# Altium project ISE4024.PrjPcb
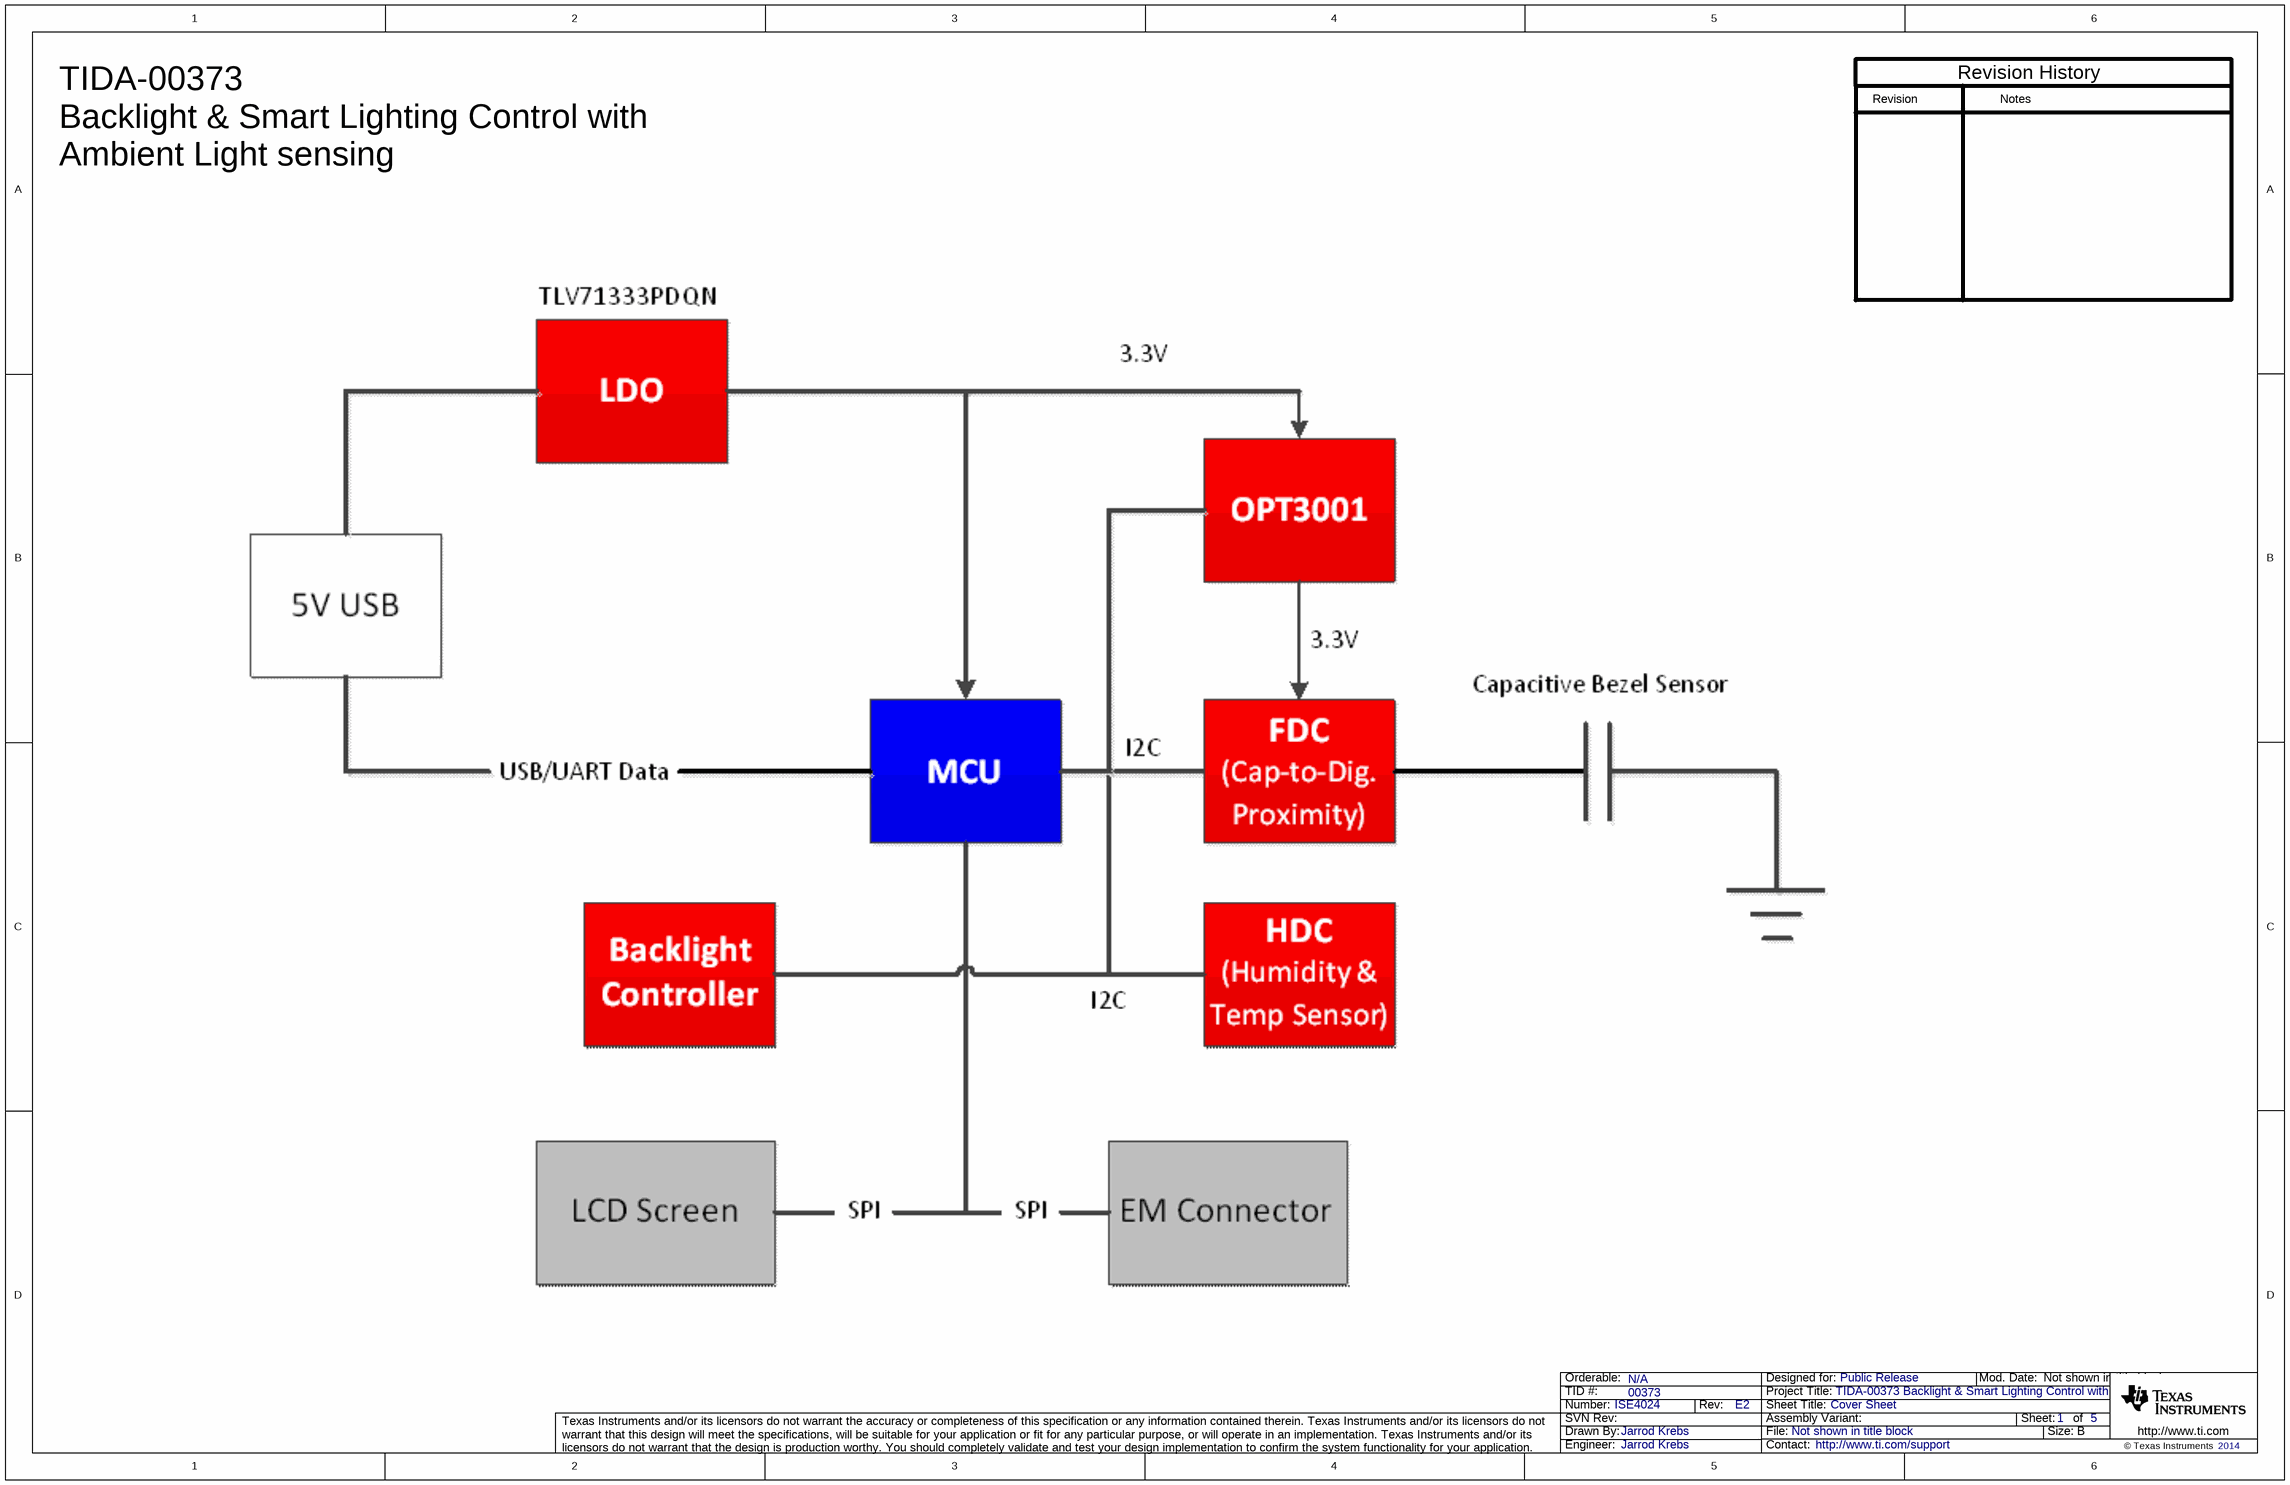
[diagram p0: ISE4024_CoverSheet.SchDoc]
CopyrightYear: 2014; EVM_Orderable: N/A; PCB_Rev: E2; PRJ_Customer: Public Release; PRJ_Engineer: Jarrod Krebs; PRJ_Number: ISE4024; PRJ_Title: TIDA-00373 Backlight & Smart Lighting Control with Ambient Light Sensing; SCH_Rev: E2; TechSupport: http://www.ti.com/support; TID: 00373
5 sheets, 138 parts. Net scope: global (net labels, ports and power ports of the same name join across sheets).
Board file: ISE4024_TID.PcbDoc
Sheets:
  ISE4024_CoverSheet.SchDoc
  ISE4024_TID_Hardware.SchDoc
  ISE4024_Sheet1.SchDoc
  ISE4024_Sheet2.SchDoc
  ISE4024_Sheet3.SchDoc

## Sheet ISE4024_CoverSheet.SchDoc: Cover Sheet
size 431 x 279 mm; Date: Not shown in title block; ApprovedBy: Not shown in title block; CheckedBy: Not shown in title block; Author: Not shown in title block; CompanyName: Not shown in title block; DrawnBy: Jarrod Krebs; Engineer: Not shown in title block; Organization: Not shown in title block; Address1: Not shown in title block; Address2: Not shown in title block; Address3: Not shown in title block; Address4: Not shown in title block; DocumentNumber: 1; Revision: Use project parameter SCH_Rev; SheetNumber: 1; SheetTotal: 5; PageSetup: Record=PageOptions¦CenterHorizontal=True¦CenterVertical=True¦PrintScale=1.00¦XCorrection=1.00¦YCorrection=1.00¦PrintKind=0¦BorderSize=5000000¦LeftOffset=0¦BottomOffset=0¦Orientation=2¦PaperLength=1000¦PaperWidth=1000¦Scale=100¦PaperSource=15¦PrintQuality=600¦MediaType=1¦DitherType=10¦PaperKind=Letter¦PrintScaleMode=1

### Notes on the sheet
- Revision
- Notes
- Revision History
- TIDA-00373
  Backlight & Smart Lighting Control with
  Ambient Light sensing

## Sheet ISE4024_TID_Hardware.SchDoc: Hardware
size 431 x 279 mm; Date: Not shown in title block; ApprovedBy: Not shown in title block; CheckedBy: Not shown in title block; Author: Not shown in title block; CompanyName: Not shown in title block; DrawnBy: Jarrod Krebs; Engineer: Not shown in title block; Organization: Not shown in title block; Address1: Not shown in title block; Address2: Not shown in title block; Address3: Not shown in title block; Address4: Not shown in title block; DocumentNumber: 2; Revision: Use project parameter SCH_Rev; SheetNumber: 2; SheetTotal: 5; PageSetup: Record=PageOptions¦CenterHorizontal=True¦CenterVertical=True¦PrintScale=1.00¦XCorrection=1.00¦YCorrection=1.00¦PrintKind=0¦BorderSize=5000000¦LeftOffset=0¦BottomOffset=0¦Orientation=2¦PaperLength=1000¦PaperWidth=1000¦Scale=100¦PaperSource=15¦PrintQuality=600¦MediaType=1¦DitherType=10¦PaperKind=Letter¦PrintScaleMode=1
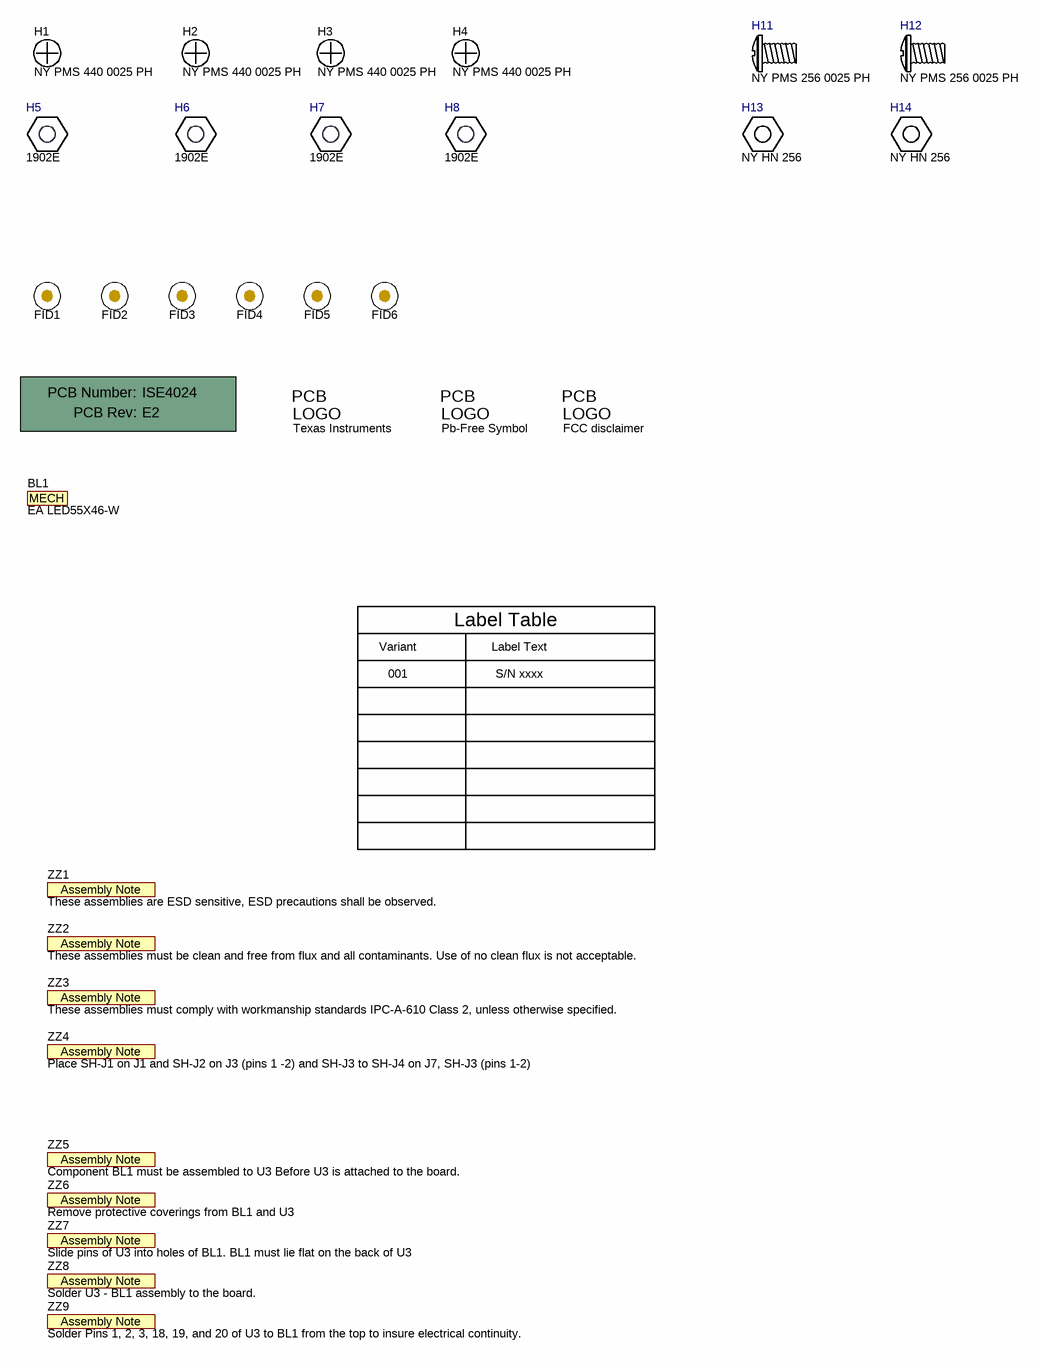
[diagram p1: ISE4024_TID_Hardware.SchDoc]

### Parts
!PCB  Printed Circuit Board  (value not drawn)  (mechanical)
BL1  EA LED55X46-W  (mechanical)
FID1  Fiducial  [Fiducial10-20]  (value not drawn)
FID2  Fiducial  [Fiducial10-20]  (value not drawn)
FID3  Fiducial  [Fiducial10-20]  (value not drawn)
FID4  Fiducial  [Fiducial10-20]  (value not drawn)
FID5  Fiducial  [Fiducial10-20]  (value not drawn)
FID6  Fiducial  [Fiducial10-20]  (value not drawn)
H1  NY PMS 440 0025 PH  [NY PMS 440 0025 PH]
H2  NY PMS 440 0025 PH  [NY PMS 440 0025 PH]
H3  NY PMS 440 0025 PH  [NY PMS 440 0025 PH]
H4  NY PMS 440 0025 PH  [NY PMS 440 0025 PH]
H5  1902E  [Keystone_1902E]
H6  1902E  [Keystone_1902E]
H7  1902E  [Keystone_1902E]
H8  1902E  [Keystone_1902E]
H11  NY PMS 256 0025 PH  (mechanical)
H12  NY PMS 256 0025 PH  (mechanical)
H13  NY HN 256  (mechanical)
H14  NY HN 256  (mechanical)
Logo1  Texas Instruments  [TI_Stacked_Overlay_Medium]  (no BOM)
Logo2  Pb-Free Symbol  [Pb-Free_Overlay_Small]  (no BOM)
Logo3  FCC disclaimer  [FCC_disclaimer]  (no BOM)
ZZ1  These assemblies are ESD sensitive, ESD precautions shall be observed.  [AssemblyNote]  (no BOM)
ZZ2  These assemblies must be clean and free from flux and all contaminants. Use of no clean flux is not acceptable.  [AssemblyNote]  (no BOM)
ZZ3  These assemblies must comply with workmanship standards IPC-A-610 Class 2, unless otherwise specified.  [AssemblyNote]  (no BOM)
ZZ4  Place SH-J1 on J1 and SH-J2 on J3 (pins 1 -2) and SH-J3 to SH-J4 on J7, SH-J3 (pins 1-2)  [AssemblyNote]  (no BOM)
ZZ5  Component BL1 must be assembled to U3 Before U3 is attached to the board.  [AssemblyNote]  (no BOM)
ZZ6  Remove protective coverings from BL1 and U3  [AssemblyNote]  (no BOM)
ZZ7  Slide pins of U3 into holes of BL1. BL1 must lie flat on the back of U3  [AssemblyNote]  (no BOM)
ZZ8  Solder U3 - BL1 assembly to the board.  [AssemblyNote]  (no BOM)
ZZ9  Solder Pins 1, 2, 3, 18, 19, and 20 of U3 to BL1 from the top to insure electrical continuity.  [AssemblyNote]  (no BOM)

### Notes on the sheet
- Variant
- Label Table
- Label Text
- 001
- S/N xxxx

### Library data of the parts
!PCB = PCB: Manufacturer: Any; PartNumber: ISE4024; SymbolCreator: a0412235
BL1 = EA LED55X46-W: LED Backlight, White; Manufacturer: Electronic Assembly; SymbolCreator: codlsc
FID1-FID6 = Fiducial: Fiducial mark.  There is nothing to buy or mount.; SymbolCreator: codlsc
H1-H4 = NY PMS 440 0025 PH: Machine Screw, Round, #4-40 x 1/4, Nylon, Philips panhead; Manufacturer: B&F Fastener Supply; CompType: Hardware; SymbolCreator: codlsc; U/M: EA
H5-H8 = 1902E: Standoff, Hex, 1"L #4-40 Nylon; Manufacturer: Keystone; CompType: Hardware; SymbolCreator: a0412235
H11 H12 = NY PMS 256 0025 PH: Nylon Screw, Panhead, Phillips, 2-56; Manufacturer: B&F Fastener Supply; SymbolCreator: a0412235
H13 H14 = NY HN 256: Nylon Nut, 2-56, 3/16"; Manufacturer: B&F Fastener Supply; SymbolCreator: a0412235
Logo1 = TI_Logo: Texas Instrument Corporate Signature; SymbolCreator: codlsc
Logo2 = Pb-Free: SymbolCreator: a0412235
Logo3 = FCC_disclaimer: SymbolCreator: codlsc
ZZ1-ZZ3 = AssemblyNote: SymbolCreator: codlsc
ZZ4 = Assembly Note: This Assembly Note will show in the PcbDoc and associated outputs; SymbolCreator: codlsc
ZZ5 = AssemblyNote: Component BL1 must be assembled to U5 Before U5 is attached to the board.; SymbolCreator: codlsc
ZZ6 = AssemblyNote: Remove protective coverings from BL1 and U5; SymbolCreator: codlsc
ZZ7 = AssemblyNote: Slide pins of U5 into holes of BL1. BL1 must lie flat on the back of U5.; SymbolCreator: codlsc
ZZ8 = AssemblyNote: Solder U5 - BL1 assembly to the board.; SymbolCreator: codlsc
ZZ9 = AssemblyNote: Solder Pins 1, 2, 3, 18, 19, and 20 of U5 to BL1 from the top to insure electrical continuity.; SymbolCreator: codlsc

## Sheet ISE4024_Sheet1.SchDoc: Power and Display
size 431 x 279 mm; Date: Not shown in title block; ApprovedBy: Not shown in title block; CheckedBy: Not shown in title block; Author: Not shown in title block; CompanyName: Not shown in title block; DrawnBy: Jarrod Krebs; Engineer: Not shown in title block; Organization: Not shown in title block; Address1: Not shown in title block; Address2: Not shown in title block; Address3: Not shown in title block; Address4: Not shown in title block; DocumentNumber: 3; Revision: Use project parameter SCH_Rev; SheetNumber: 3; SheetTotal: 5; PageSetup: Record=PageOptions¦CenterHorizontal=True¦CenterVertical=True¦PrintScale=1.00¦XCorrection=1.00¦YCorrection=1.00¦PrintKind=0¦BorderSize=5000000¦LeftOffset=0¦BottomOffset=0¦Orientation=2¦PaperLength=1000¦PaperWidth=1000¦Scale=100¦PaperSource=15¦PrintQuality=600¦MediaType=1¦DitherType=10¦PaperKind=Letter¦PrintScaleMode=1
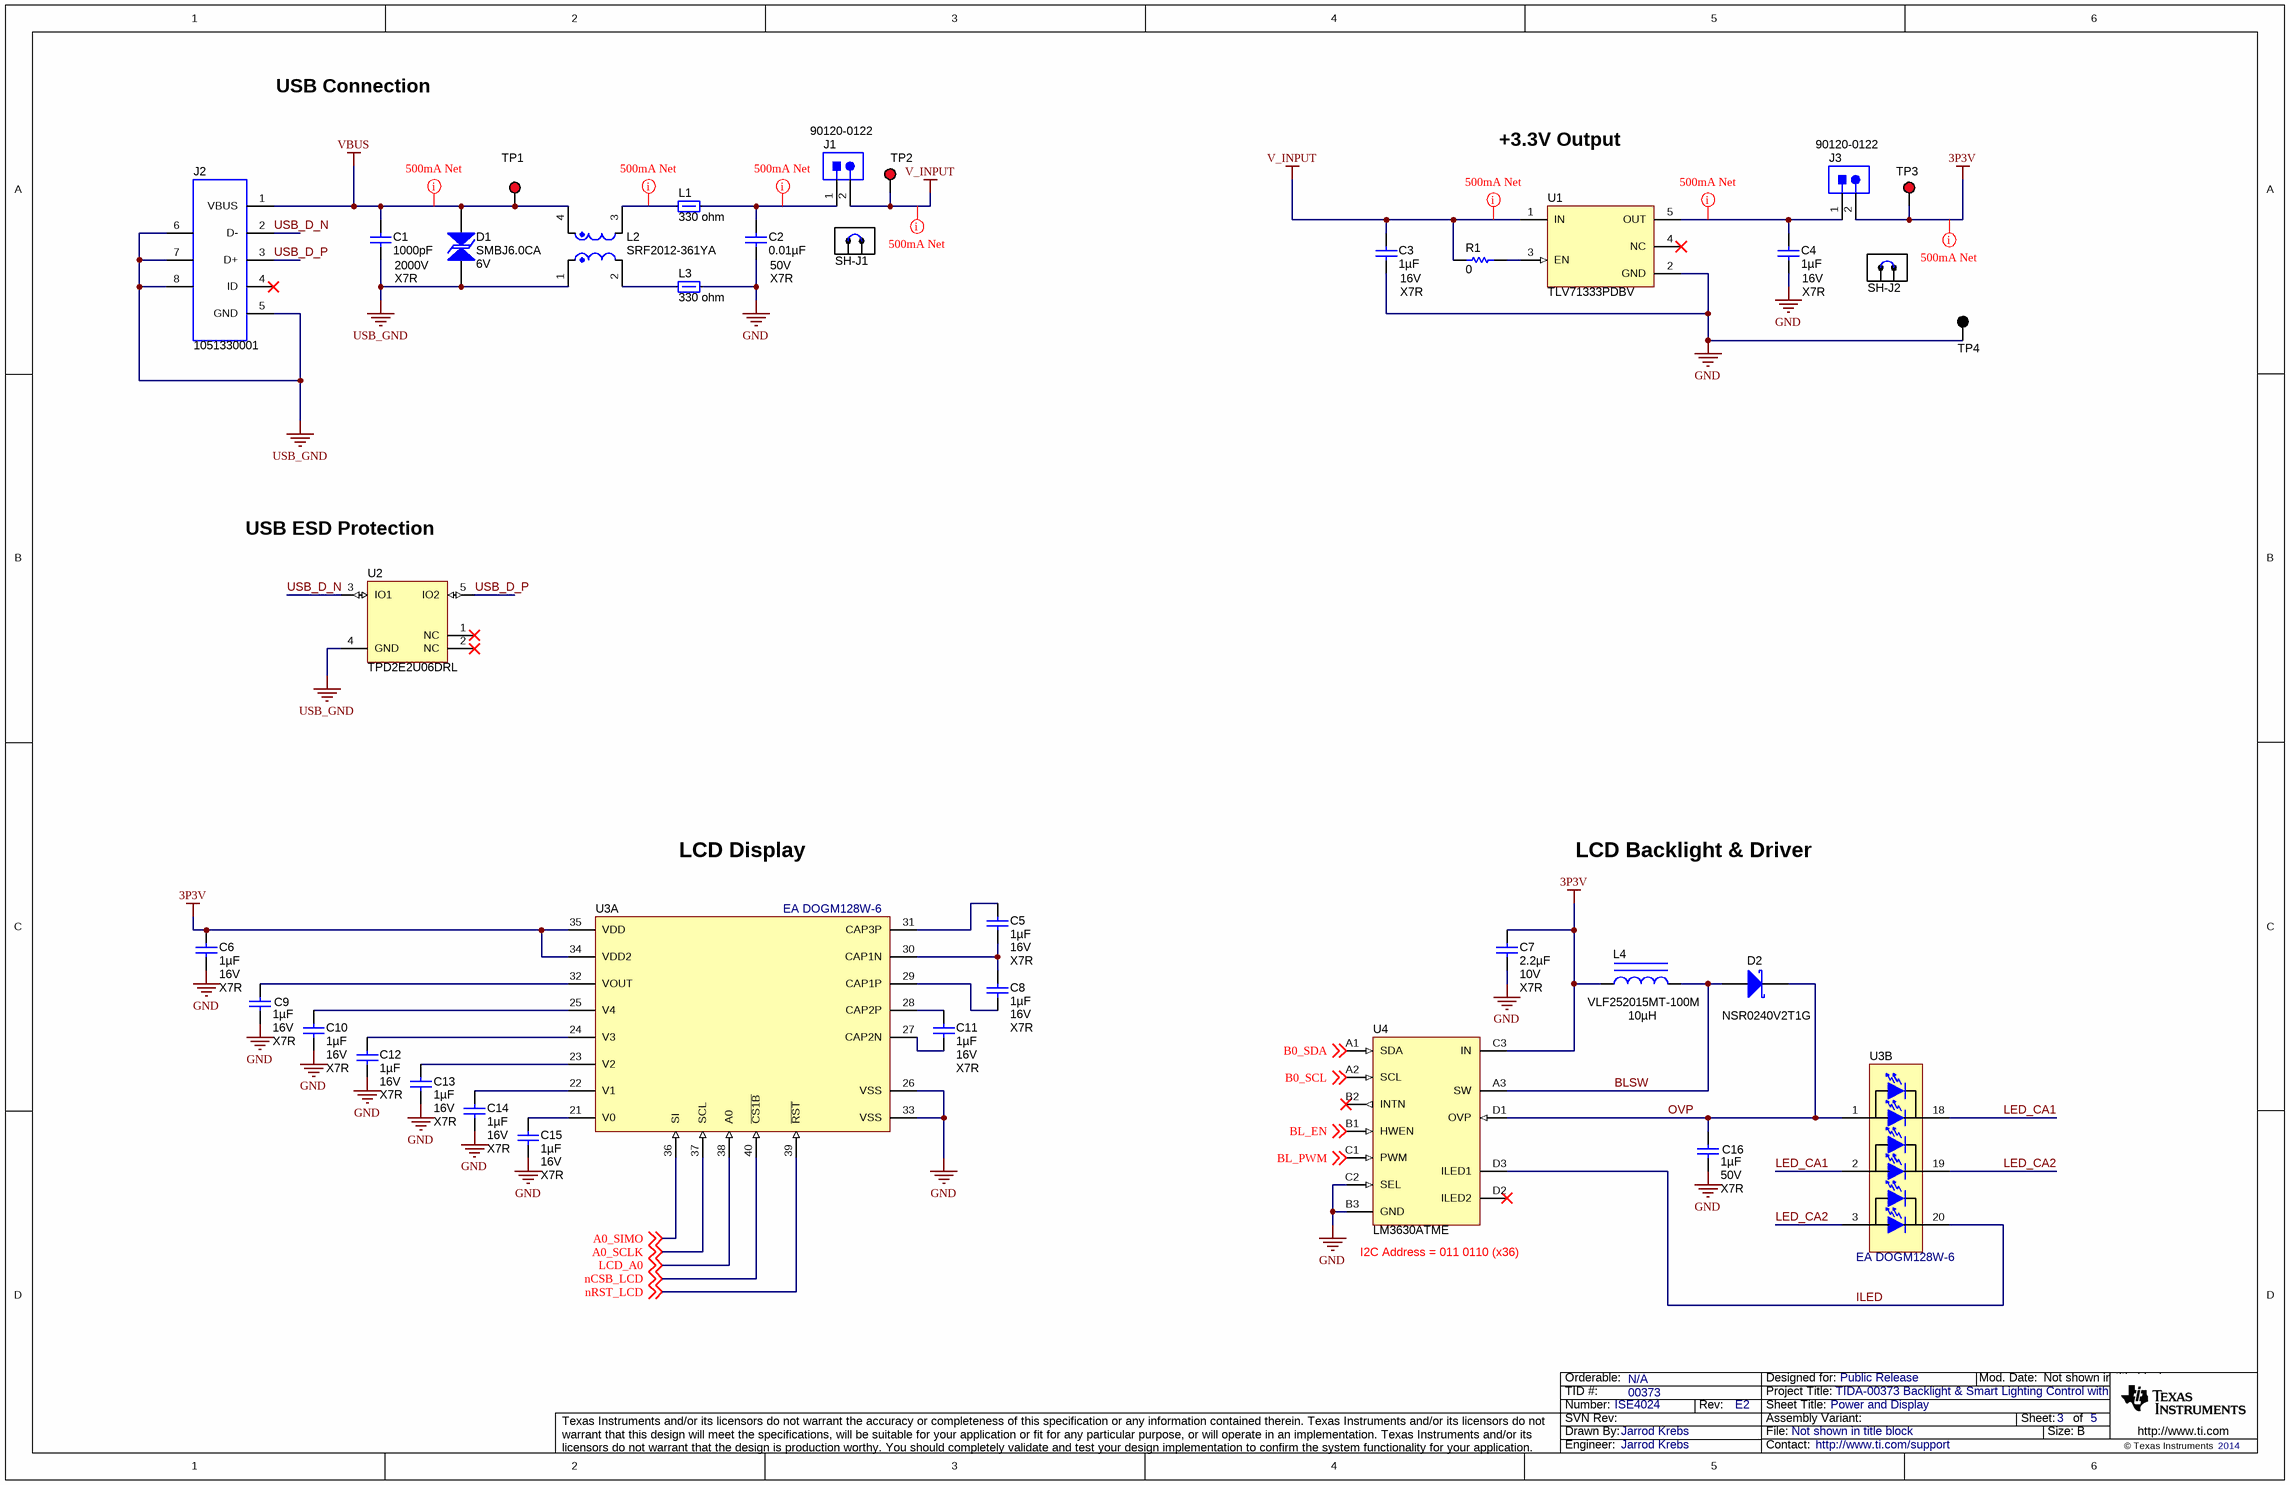
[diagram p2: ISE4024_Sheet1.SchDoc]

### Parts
C1  VDC_V: 2000V  TempCo: X7R  ValueDisplayed: 1000pF  [1206_190]  (hidden comment: 202R18W102KV4E)
C2  ValueDisplayed: 0.01µF  Value2: 50V  TempCo: X7R  [0805_HV]  (hidden comment: 08055C103JAT2A)
C3  ValueDisplayed: 1µF  Value2: 16V  TempCo: X7R  [0603]  (hidden comment: C1608X7R1C105K)
C4  ValueDisplayed: 1µF  Value2: 16V  TempCo: X7R  [0603]  (hidden comment: C1608X7R1C105K)
C5  ValueDisplayed: 1µF  Value2: 16V  TempCo: X7R  [0603]  (hidden comment: C1608X7R1C105K)
C6  ValueDisplayed: 1µF  Value2: 16V  TempCo: X7R  [0603]  (hidden comment: C1608X7R1C105K)
C7  ValueDisplayed: 2.2µF  Value2: 10V  TempCo: X7R  [0603]  (hidden comment: GRM188R71A225KE15D)
C8  ValueDisplayed: 1µF  Value2: 16V  TempCo: X7R  [0603]  (hidden comment: C1608X7R1C105K)
C9  ValueDisplayed: 1µF  Value2: 16V  TempCo: X7R  [0603]  (hidden comment: C1608X7R1C105K)
C10  ValueDisplayed: 1µF  Value2: 16V  TempCo: X7R  [0603]  (hidden comment: C1608X7R1C105K)
C11  ValueDisplayed: 1µF  Value2: 16V  TempCo: X7R  [0603]  (hidden comment: C1608X7R1C105K)
C12  ValueDisplayed: 1µF  Value2: 16V  TempCo: X7R  [0603]  (hidden comment: C1608X7R1C105K)
C13  ValueDisplayed: 1µF  Value2: 16V  TempCo: X7R  [0603]  (hidden comment: C1608X7R1C105K)
C14  ValueDisplayed: 1µF  Value2: 16V  TempCo: X7R  [0603]  (hidden comment: C1608X7R1C105K)
C15  ValueDisplayed: 1µF  Value2: 16V  TempCo: X7R  [0603]  (hidden comment: C1608X7R1C105K)
C16  ValueDisplayed: 1µF  Value2: 50V  TempCo: X7R  [0603]  (hidden comment: UMK107AB7105KA-T)
D1  SMBJ6.0CA  value 6V  [SMB]
D2  NSR0240V2T1G  [SOD-523]
J1  90120-0122  [CONN_90120-0122]
J2  1051330001  [Molex_1051330001]
J3  90120-0122  [CONN_90120-0122]
L1  value 330 ohm  [0603]  (hidden comment: BLM18SG331TN1D)
L2  SRF2012-361YA  [SRF2012A]
L3  value 330 ohm  [0603]  (hidden comment: BLM18SG331TN1D)
L4  VLF252015MT-100M  ValueDisplayed: 10µH  [IND_VLF252015]
R1  ValueDisplayed: 0  [0603]  (hidden comment: CRCW06030000Z0EA)
SH-J1  2SN-BK-G  [2SN-BK-G]  (value not drawn)
SH-J2  2SN-BK-G  [2SN-BK-G]  (value not drawn)
TP1  5000  [Keystone5000]  (value not drawn)
TP2  5000  [Keystone5000]  (value not drawn)
TP3  5000  [Keystone5000]  (value not drawn)
TP4  5001  [Keystone5001]  (value not drawn)
U1  TLV71333PDBV  [DBV0005A_N]
U2  TPD2E2U06DRL  [DRL0005A]
U3  EA DOGM128W-6  [LCD-MODULE_EA DOGM128W-6]  (parts A,B of 2)
U4  LM3630ATME  [YFQ0012AKAR]

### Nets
3P3V: C6.1 C7.1 J3.2 L4.1 TP3.1 U3.34(VDD2) U3.35(VDD) U4.C3(IN)
GND: C2.2 C3.2 C4.2 C6.2 C7.2 C9.2 C10.2 C12.2 C13.2 C14.2 C15.2 C16.2 L3.2 TP4.1 U1.2(GND) U3.26(VSS) U3.33(VSS) U4.B3(GND) U4.C2(SEL)
USB_GND: C1.2 D1.1 J2.5(GND) J2.6(Shield) J2.7(Shield) J2.8(Shield) L2.1 U2.4(GND)
V_INPUT: C3.1 J1.2 R1.1 TP2.1 U1.1(IN)
VBUS: C1.1 D1.2 J2.1(VBUS) L2.4 TP1.1
A0_SCLK: U3.37(SCL) ; off-sheet A0_SCLK
A0_SIMO: U3.36(SI) ; off-sheet A0_SIMO
B0_SCL: U4.A2(SCL) ; off-sheet B0_SCL
B0_SDA: U4.A1(SDA) ; off-sheet B0_SDA
BL_EN: U4.B1(HWEN) ; off-sheet BL_EN
BL_PWM: U4.C1(PWM) ; off-sheet BL_PWM
BLSW: D2.2(A) L4.2 U4.A3(SW)
ILED: U3.20(K) U4.D3(ILED1)
LCD_A0: U3.38(A0) ; off-sheet LCD_A0
LED_CA1: U3.2(A) U3.18(K)
LED_CA2: U3.3(A) U3.19(K)
nCSB_LCD: U3.40(~{CS1B}) ; off-sheet nCSB_LCD
nRST_LCD: U3.39(~{RST}) ; off-sheet nRST_LCD
OVP: C16.1 D2.1(K) U3.1(A) U4.D1(OVP)
USB_D_N: J2.2(D-) U2.3(IO1)
USB_D_P: J2.3(D+) U2.5(IO2)
NetC2_1: C2.1 J1.1 L1.2
NetC4_1: C4.1 J3.1 U1.5(OUT)
NetC5_1: C5.1 U3.31(CAP3P)
NetC5_2: C5.2 C8.1 U3.30(CAP1N)
NetC8_2: C8.2 U3.29(CAP1P)
NetC9_1: C9.1 U3.32(VOUT)
NetC10_1: C10.1 U3.25(V4)
NetC11_1: C11.1 U3.28(CAP2P)
NetC11_2: C11.2 U3.27(CAP2N)
NetC12_1: C12.1 U3.24(V3)
NetC13_1: C13.1 U3.23(V2)
NetC14_1: C14.1 U3.22(V1)
NetC15_1: C15.1 U3.21(V0)
NetL1_1: L1.1 L2.3
NetL2_2: L2.2 L3.1
NetR1_2: R1.2 U1.3(EN)

Not connected (* = marked no-connect by the designer): J2 4(ID)*; U1 4(NC)*; U2 1(NC)* 2(NC)*; U4 B2(INTN)* D2(ILED2)*

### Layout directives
rule Width Constraint [Pref Width = 25mil    Min Width = 5mil    Max Width = 100mil]: 3P3V, NetC2_1, NetC4_1, NetL1_1, V_INPUT, VBUS

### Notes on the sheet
- USB Connection
- +3.3V Output
- USB ESD Protection
- LCD Display
- LCD Backlight & Driver
- (near U4) I2C Address = 011 0110 (x36)

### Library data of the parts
C1 = 202R18W102KV4E: CAP, CERM, 1000 pF, 2000 V, +/- 10%, X7R, 1206_190; Manufacturer: Johanson Technology; Polarized: N; CompType: Capacitor; Value: 1000pF; U/M: EA; Cap_F: 0.000000001; Tolerance_%: 10; Value1: Unknown; TaMin_C: -55; TaMax_C: 125
C2 = 08055C103JAT2A: CAP, CERM, 0.01 µF, 50 V, +/- 5%, X7R, 0805; Manufacturer: AVX; Polarized: N; CompType: Capacitor; Value: 0.01uF; U/M: EA; Cap_F: 0.00000001; Tolerance_%: 5; ESR_ohm: 0.078; Value1: 0.078 ohm; VDC_V: 50; TaMin_C: -55; TaMax_C: 125; Cap_Case: 0805
C3 C4 = C1608X7R1C105K: CAP, CERM, 1 µF, 16 V, +/- 10%, X7R, 0603; Manufacturer: TDK; Polarized: N; CompType: Capacitor; Value: 1uF; U/M: EA; Cap_F: 0.000001; Tolerance_%: 10; ESR_ohm: 0.0057; Value1: 0.0057 ohm; VDC_V: 16; TaMin_C: -55; TaMax_C: 125
C5 C6 C8-C15 = C1608X7R1C105K: CAP, CERM, 1uF, 16V, +/-10%, X7R, 0603; Manufacturer: TDK; Polarized: N; CompType: Capacitor; U/M: EA; Cap_F: 0.000001; Tolerance_%: 10; ESR_Ohm: 0.0057; Value1: 0.0057 ohm; VDC_V: 16; TaMin_C: -55; TaMax_C: 125
C7 = GRM188R71A225KE15D: CAP, CERM, 2.2uF, 10V, +/-10%, X7R, 0603; Manufacturer: MuRata; Polarized: N; CompType: Capacitor; U/M: EA; Cap_F: 0.0000022; Tolerance_%: 10; ESR_Ohm: 0.009; Value1: 0.009 ohm; TaMin_C: -55; TaMax_C: 125
C16 = UMK107AB7105KA-T: CAP, CERM, 1uF, 50V, +/-10%, X7R, 0603; Manufacturer: Taiyo Yuden; Polarized: N; CompType: Capacitor; U/M: EA; Cap_F: 0.000001; Tolerance_%: 10; Value1: Unknown; VDC_V: 50; TaMin_C: -55; TaMax_C: 125
D1 = SMBJ6.0CA: Diode, TVS, Bi, 6 V, 600 W, SMB; Manufacturer: Littelfuse; U/M: EA; Power_W: 600; Vr_V: 6; Value1: 600W; RJA_CperW: 100
D2 = NSR0240V2T1G: Diode, Schottky, 40V, 0.25A, SOD-523; Manufacturer: ON Semiconductor; U/M: EA; Vf_V: 0.7; Value2: 0.7V; Io_A: 0.25; Vr_V: 40; TJmax_C: 150; RJC_CperW: 600
J1 J3 = 90120-0122: Header, 100mil, 2x1, Tin, TH; Manufacturer: Molex; SymbolCreator: a0412235; U/M: EA
J2 = 1051330001: Connector, Receptacle, USB TYPE B, Vertical, TH; Manufacturer: Molex; SymbolCreator: Altium; U/M: EA
L1 L3 = BLM18SG331TN1D: Ferrite Bead, 330 ohm @ 100 MHz, 1.5 A, 0603; Manufacturer: MuRata; Imax_A: 1.5; DCR_ohm: 0.07; Value1: 0.07 ohm; Value2: 1.5A; ZTyp@100MHz_Ohm: 330
L2 = SRF2012-361YA: Inductor, Wirewound, Ferrite, , 0.3 A, 0.45 ohm, SMD; Manufacturer: Bourns; SymbolCreator: a0411947; Imax_A: 0.3; DCR_ohm: 0.45; Value2: 0.3A
L4 = VLF252015MT-100M: Inductor, Shielded, Ferrite, 10uH, 0.47A, 0.24 ohm, SMD; Manufacturer: TDK; Ind_H: 10.0E-6; Imax_A: 0.47; Irms: 0.94A @ 40C rise; Isat: 0.47A @ 30% inductance drop; DCR_ohm: 0.24
R1 = CRCW06030000Z0EA: RES, 0, 5%, 0.1 W, 0603; Manufacturer: Vishay-Dale; CompType: Resistor; Value: 0; Value_Code: 0000; Tolerance_%: 5; Power_W: 0.1; Value2: 0.1W; VDC_V: 75; TempCo: 200 ppm/C; EIA_Code: E24; U/M: EA
SH-J1 SH-J2 = 2SN-BK-G: Shunt, 2mm, Gold plated, Black; Manufacturer: Samtec; Value: 1x2; Note: You can "mate" this to a header by matching the designator.  i.e. use SH-J3 for header J3
TP1-TP3 = 5000: Test Point, Miniature, Red, TH; Manufacturer: Keystone; CompType: Test Point Loop; U/M: EA
TP4 = 5001: Test Point, Miniature, Black, TH; Manufacturer: Keystone; CompType: Test Point Loop; U/M: EA
U1 = TLV71333PDBV: Capacitor-Free, 150-mA, Low-Dropout Regulator with Foldback Current Limit for Portable Devices, DBV0005A; Alternate Manufacturer: None; Manufacturer: Texas Instruments; SymbolCreator: a0411947; CompType: IC; U/M: EA
U2 = TPD2E2U06DRL: DUAL CHANNEL HIGH SPEED ESD PROTECTION DEVICE, DRL0005A; Manufacturer: Texas Instruments; SymbolCreator: a0411947; CompType: IC; U/M: EA
U3 = EA DOGM128W-6: Module, 128x64-pixel graphics display; Manufacturer: Electronic Assembly; SymbolCreator: a0799628
U4 = LM3630ATME: LM3630A High-Efficiency Dual-String White LED Driver, YFQ0012AKAR; Alternate Manufacturer: None; Manufacturer: Texas Instruments; SymbolCreator: a0411947; CompType: IC; U/M: EA

## Sheet ISE4024_Sheet2.SchDoc: MCU and EM Connector
size 431 x 279 mm; Date: Not shown in title block; ApprovedBy: Not shown in title block; CheckedBy: Not shown in title block; Author: Not shown in title block; CompanyName: Not shown in title block; DrawnBy: Jarrod Krebs; Engineer: Not shown in title block; Organization: Not shown in title block; Address1: Not shown in title block; Address2: Not shown in title block; Address3: Not shown in title block; Address4: Not shown in title block; DocumentNumber: 4; Revision: Use project parameter SCH_Rev; SheetNumber: 4; SheetTotal: 5; PageSetup: Record=PageOptions¦CenterHorizontal=True¦CenterVertical=True¦PrintScale=1.00¦XCorrection=1.00¦YCorrection=1.00¦PrintKind=0¦BorderSize=5000000¦LeftOffset=0¦BottomOffset=0¦Orientation=2¦PaperLength=1000¦PaperWidth=1000¦Scale=100¦PaperSource=15¦PrintQuality=600¦MediaType=1¦DitherType=10¦PaperKind=Letter¦PrintScaleMode=1
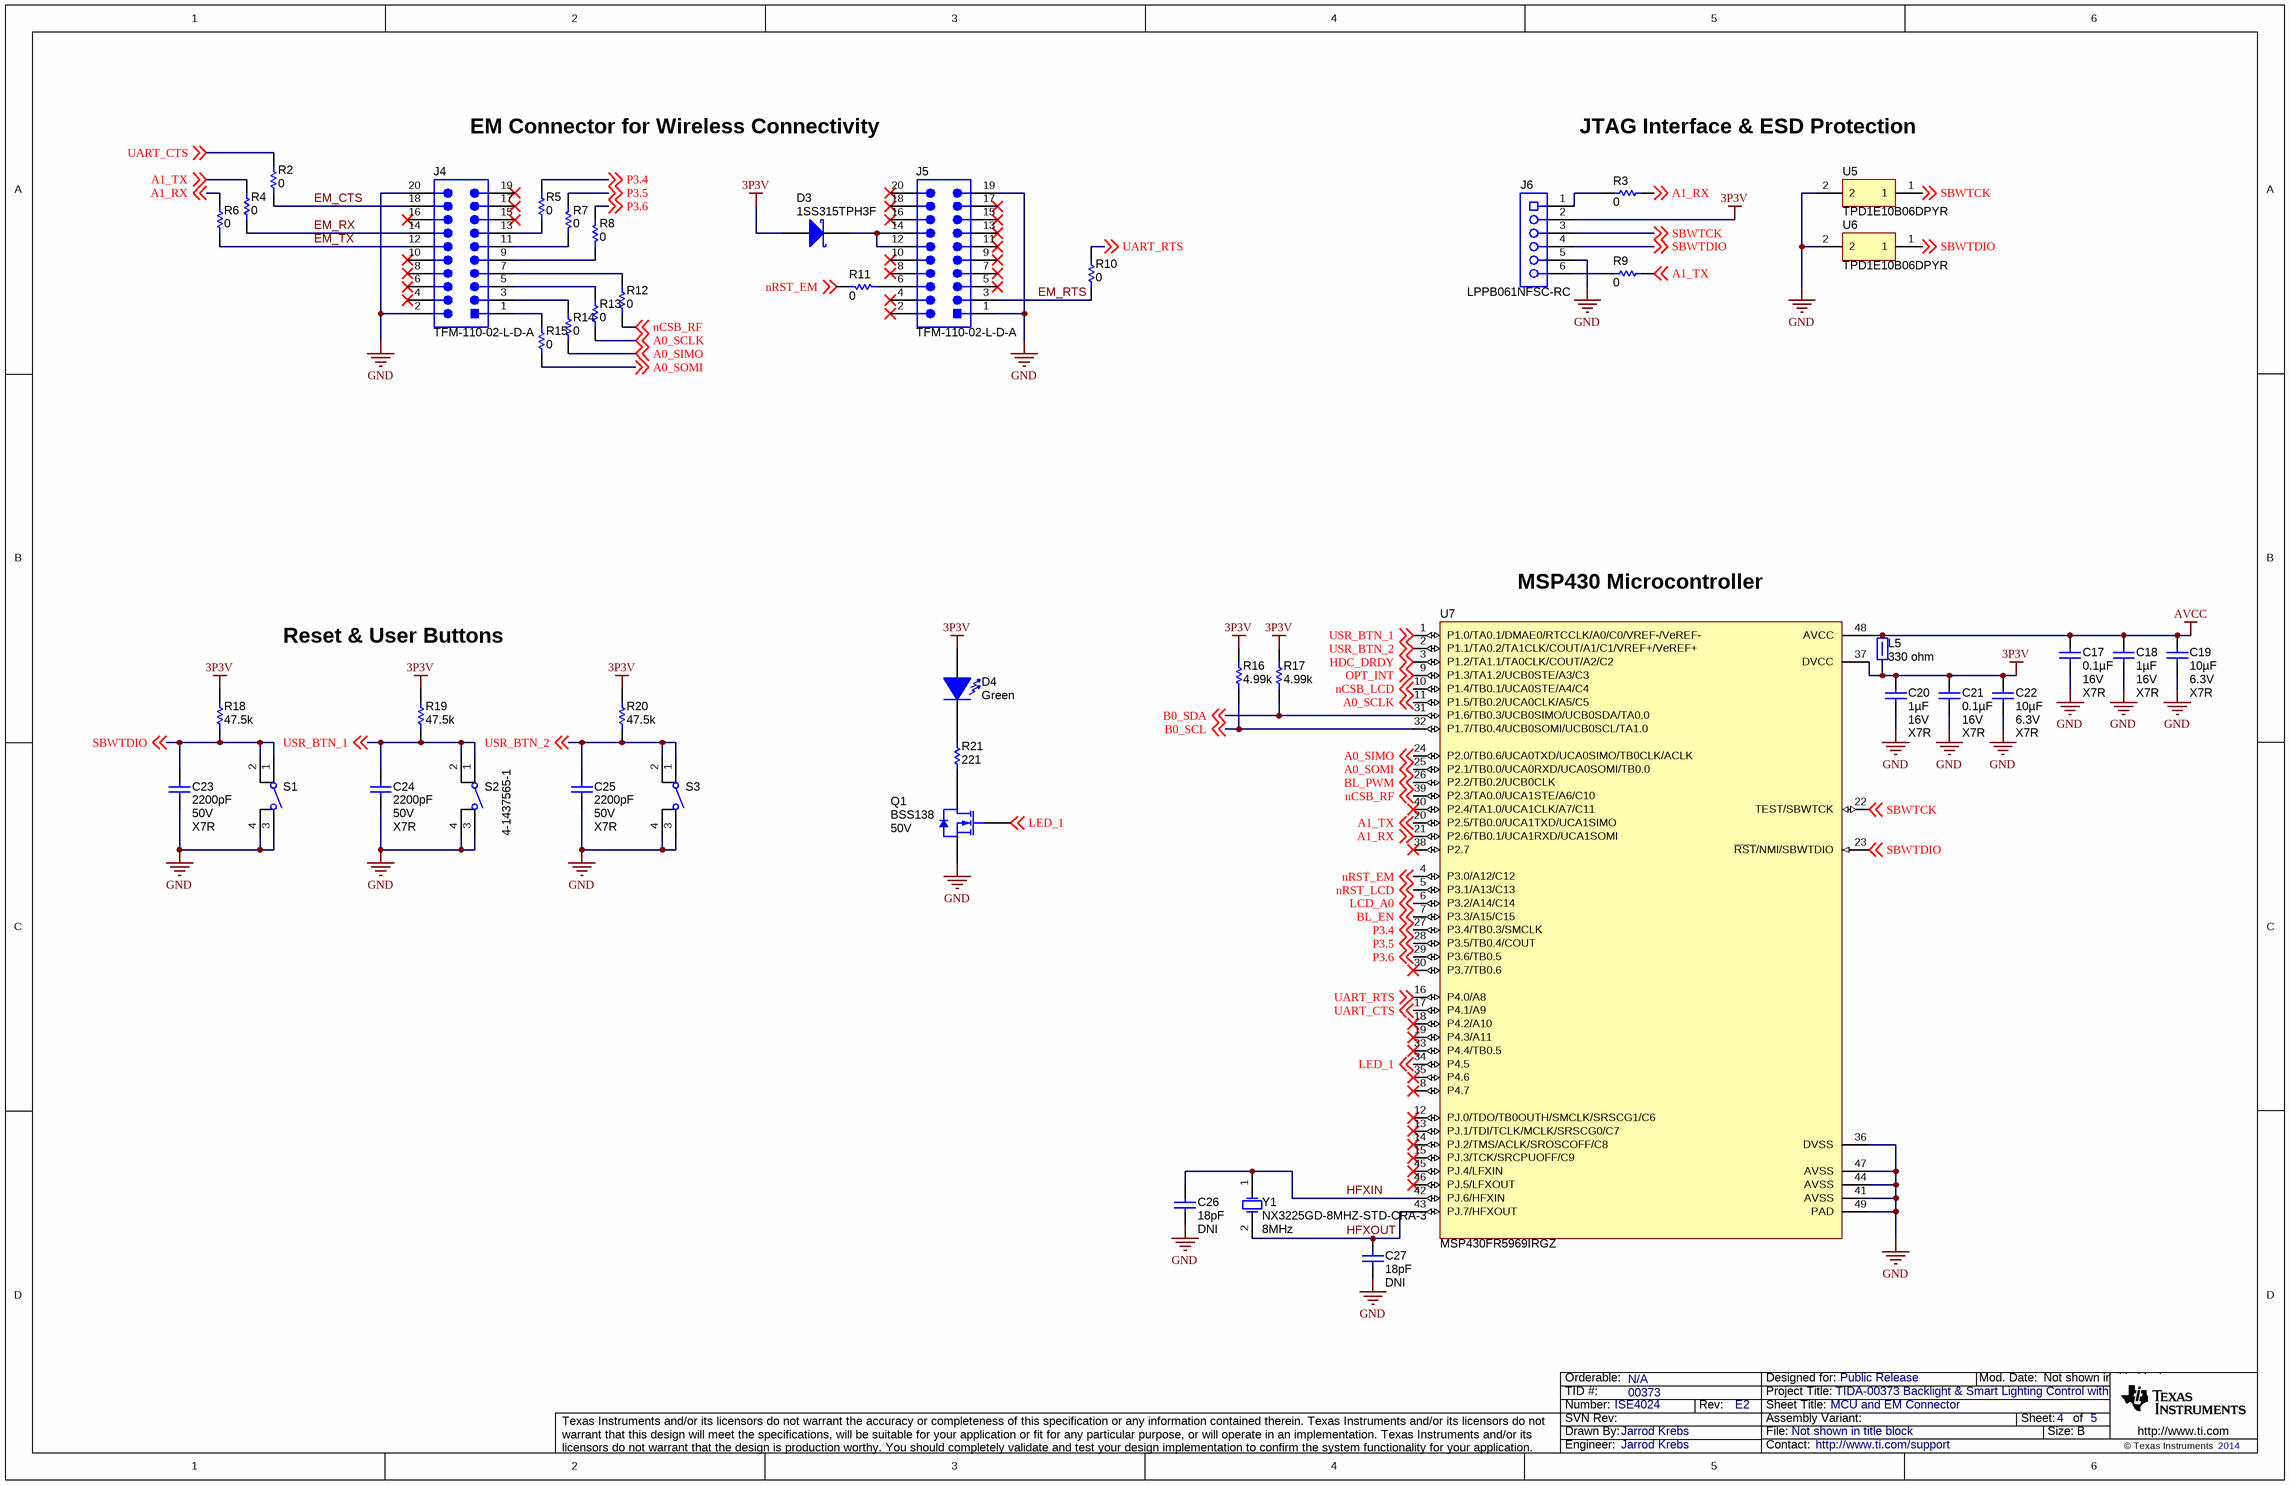
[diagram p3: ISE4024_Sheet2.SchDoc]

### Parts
C17  ValueDisplayed: 0.1µF  Value2: 16V  TempCo: X7R  [0402]  (hidden comment: GRM155R71C104KA88D)
C18  ValueDisplayed: 1µF  Value2: 16V  TempCo: X7R  [0603]  (hidden comment: C1608X7R1C105K)
C19  ValueDisplayed: 10µF  Value2: 6.3V  TempCo: X7R  [0805_HV]  (hidden comment: C2012X7R0J106M125AB)
C20  ValueDisplayed: 1µF  Value2: 16V  TempCo: X7R  [0603]  (hidden comment: C1608X7R1C105K)
C21  ValueDisplayed: 0.1µF  Value2: 16V  TempCo: X7R  [0402]  (hidden comment: GRM155R71C104KA88D)
C22  ValueDisplayed: 10µF  Value2: 6.3V  TempCo: X7R  [0805_HV]  (hidden comment: C2012X7R0J106M125AB)
C23  ValueDisplayed: 2200pF  Value2: 50V  TempCo: X7R  [0402]  (hidden comment: C1005X7R1H222K)
C24  ValueDisplayed: 2200pF  Value2: 50V  TempCo: X7R  [0402]  (hidden comment: C1005X7R1H222K)
C25  ValueDisplayed: 2200pF  Value2: 50V  TempCo: X7R  [0402]  (hidden comment: C1005X7R1H222K)
C26  ValueDisplayed: 18pF  [0603]  (hidden comment: GRM1885C2A180JA01D)
C27  ValueDisplayed: 18pF  [0603]  (hidden comment: GRM1885C2A180JA01D)
D3  1SS315TPH3F  [sod-323]
D4  value Green  [SML-P1_GREEN]  (hidden comment: SML-P12PTT86)
J4  TFM-110-02-L-D-A  [Samtec_TFM-110-02-L-D-A]
J5  TFM-110-02-L-D-A  [Samtec_TFM-110-02-L-D-A]
J6  LPPB061NFSC-RC  [Sullins_LPPB061NFSC-RC]
L5  value 330 ohm  [0603]  (hidden comment: BLM18SG331TN1D)
Q1  BSS138  value 50V  [SOT-23]
R2  value 0  [0402]  (hidden comment: CRCW04020000Z0ED)
R3  value 0  [0402]  (hidden comment: CRCW04020000Z0ED)
R4  value 0  [0402]  (hidden comment: CRCW04020000Z0ED)
R5  value 0  [0402]  (hidden comment: CRCW04020000Z0ED)
R6  value 0  [0402]  (hidden comment: CRCW04020000Z0ED)
R7  value 0  [0402]  (hidden comment: CRCW04020000Z0ED)
R8  value 0  [0402]  (hidden comment: CRCW04020000Z0ED)
R9  value 0  [0402]  (hidden comment: CRCW04020000Z0ED)
R10  value 0  [0402]  (hidden comment: CRCW04020000Z0ED)
R11  value 0  [0402]  (hidden comment: CRCW04020000Z0ED)
R12  value 0  [0402]  (hidden comment: CRCW04020000Z0ED)
R13  value 0  [0402]  (hidden comment: CRCW04020000Z0ED)
R14  value 0  [0402]  (hidden comment: CRCW04020000Z0ED)
R15  value 0  [0402]  (hidden comment: CRCW04020000Z0ED)
R16  value 4.99k  [0402]  (hidden comment: CRCW04024K99FKED)
R17  value 4.99k  [0402]  (hidden comment: CRCW04024K99FKED)
R18  ValueDisplayed: 47.5k  [0402]  (hidden comment: CRCW040247K5FKED)
R19  ValueDisplayed: 47.5k  [0402]  (hidden comment: CRCW040247K5FKED)
R20  ValueDisplayed: 47.5k  [0402]  (hidden comment: CRCW040247K5FKED)
R21  value 221  [0402]  (hidden comment: CRCW0402221RFKED)
S1  4-1437565-1  [SW_FSM4JSMA]  (value not drawn)
S2  4-1437565-1  [SW_FSM4JSMA]
S3  4-1437565-1  [SW_FSM4JSMA]  (value not drawn)
U5  TPD1E10B06DPYR  [DPY0002A]
U6  TPD1E10B06DPYR  [DPY0002A]
U7  MSP430FR5969IRGZ  [RGZ0048B]
Y1  NX3225GD-8MHZ-STD-CRA-3  Frequency: 8MHz  [NDK_NX3225GD]

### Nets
3P3V: C20.2 C21.2 C22.1 D3.2(A) D4.2(A) J6.2 L5.1 R16.2 R17.2 R18.2 R19.2 R20.2 U7.37(DVCC)
AVCC: C17.2 C18.2 C19.1 L5.2 U7.48(AVCC)
GND: C17.1 C18.1 C19.2 C20.1 C21.1 C22.2 C23.1 C24.1 C25.1 C26.2 C27.2 J4.2 J4.20 J5.1 J5.19 J6.5 Q1.2(S) S1.3 S1.4 S2.3 S2.4 S3.3 S3.4 U5.2 U6.2 U7.36(DVSS) U7.41(AVSS) U7.44(AVSS) U7.47(AVSS) U7.49(PAD)
A0_SCLK: R13.2 U7.11(P1.5/TB0.2/UCA0CLK/A5/C5) ; off-sheet A0_SCLK
A0_SIMO: R14.2 U7.24(P2.0/TB0.6/UCA0TXD/UCA0SIMO/TB0CLK/ACLK) ; off-sheet A0_SIMO
A0_SOMI: R15.1 U7.25(P2.1/TB0.0/UCA0RXD/UCA0SOMI/TB0.0) ; off-sheet A0_SOMI
A1_RX: R3.1 R6.1 U7.21(P2.6/TB0.1/UCA1RXD/UCA1SOMI) ; off-sheet A1_RX
A1_TX: R4.1 R9.1 U7.20(P2.5/TB0.0/UCA1TXD/UCA1SIMO) ; off-sheet A1_TX
B0_SCL: R16.1 U7.32(P1.7/TB0.4/UCB0SOMI/UCB0SCL/TA1.0) ; off-sheet B0_SCL
B0_SDA: R17.1 U7.31(P1.6/TB0.3/UCB0SIMO/UCB0SDA/TA0.0) ; off-sheet B0_SDA
BL_EN: U7.7(P3.3/A15/C15) ; off-sheet BL_EN
BL_PWM: U7.26(P2.2/TB0.2/UCB0CLK) ; off-sheet BL_PWM
EM_CTS: J4.18 R2.1
EM_RTS: J5.3 R10.2
EM_RX: J4.14 R4.2
EM_TX: J4.12 R6.2
HDC_DRDY: U7.3(P1.2/TA1.1/TA0CLK/COUT/A2/C2) ; off-sheet HDC_DRDY
HFXIN: C26.1 U7.42(PJ.6/HFXIN) Y1.1(OSC1)
HFXOUT: C27.1 U7.43(PJ.7/HFXOUT) Y1.2(OSC2)
LCD_A0: U7.6(P3.2/A14/C14) ; off-sheet LCD_A0
LED_1: Q1.1(G) U7.34(P4.5) ; off-sheet LED_1
nCSB_LCD: U7.10(P1.4/TB0.1/UCA0STE/A4/C4) ; off-sheet nCSB_LCD
nCSB_RF: R12.2 U7.39(P2.3/TA0.0/UCA1STE/A6/C10) ; off-sheet nCSB_RF
nRST_EM: R11.2 U7.4(P3.0/A12/C12) ; off-sheet nRST_EM
nRST_LCD: U7.5(P3.1/A13/C13) ; off-sheet nRST_LCD
OPT_INT: U7.9(P1.3/TA1.2/UCB0STE/A3/C3) ; off-sheet OPT_INT
P3.4: R5.2 U7.27(P3.4/TB0.3/SMCLK) ; off-sheet P3.4
P3.5: R7.1 U7.28(P3.5/TB0.4/COUT) ; off-sheet P3.5
P3.6: R8.1 U7.29(P3.6/TB0.5) ; off-sheet P3.6
SBWTCK: J6.3 U5.1 U7.22(TEST/SBWTCK) ; off-sheet SBWTCK
SBWTDIO: C23.2 J6.4 R18.1 S1.1 S1.2 U6.1 U7.23(~{RST}/NMI/SBWTDIO) ; off-sheet SBWTDIO
UART_CTS: R2.2 U7.17(P4.1/A9) ; off-sheet UART_CTS
UART_RTS: R10.1 U7.16(P4.0/A8) ; off-sheet UART_RTS
USR_BTN_1: C24.2 R19.1 S2.1 S2.2 U7.1(P1.0/TA0.1/DMAE0/RTCCLK/A0/C0/VREF-/VeREF-) ; off-sheet USR_BTN_1
USR_BTN_2: C25.2 R20.1 S3.1 S3.2 U7.2(P1.1/TA0.2/TA1CLK/COUT/A1/C1/VREF+/VeREF+) ; off-sheet USR_BTN_2
NetD3_1: D3.1(K) J5.12 J5.14
NetD4_1: D4.1(K) R21.2
NetJ4_1: J4.1 R15.2
NetJ4_3: J4.3 R14.1
NetJ4_5: J4.5 R13.1
NetJ4_7: J4.7 R12.1
NetJ4_9: J4.9 R8.2
NetJ4_11: J4.11 R7.2
NetJ4_13: J4.13 R5.1
NetJ5_6: J5.6 R11.1
NetJ6_1: J6.1 R3.2
NetJ6_6: J6.6 R9.2
NetQ1_3: Q1.3(D) R21.1

Not connected (* = marked no-connect by the designer): J4 4* 6* 8* 10* 15* 16* 17* 19*; J5 2* 4* 5* 7* 8* 9* 10* 11* 13* 15* 16* 17* 18* 20*; U7 8(P4.7)* 12(PJ.0/TDO/TB0OUTH/SMCLK/SRSCG1/C6)* 13(PJ.1/TDI/TCLK/MCLK/SRSCG0/C7)* 14(PJ.2/TMS/ACLK/SROSCOFF/C8)* 15(PJ.3/TCK/SRCPUOFF/C9)* 18(P4.2/A10)* 19(P4.3/A11)* 30(P3.7/TB0.6)* 33(P4.4/TB0.5)* 35(P4.6)* 38(P2.7)* 40(P2.4/TA1.0/UCA1CLK/A7/C11)* 45(PJ.4/LFXIN)* 46(PJ.5/LFXOUT)*

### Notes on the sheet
- EM Connector for Wireless Connectivity
- JTAG Interface & ESD Protection
- Reset & User Buttons
- (near U7) MSP430 Microcontroller

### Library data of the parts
C17 C21 = GRM155R71C104KA88D: CAP, CERM, 0.1uF, 16V, +/-10%, X7R, 0402; Manufacturer: MuRata; Polarized: N; CompType: Capacitor; U/M: EA; Cap_F: 0.0000001; Tolerance_%: 10; Value1: Unknown; VDC_V: 16; TaMin_C: -55; TaMax_C: 125
C18 C20 = C1608X7R1C105K: as C5 on sheet ISE4024_Sheet1
C19 C22 = C2012X7R0J106M125AB: CAP, CERM, 10 µF, 6.3 V, +/- 20%, X7R, 0805; Manufacturer: TDK; Polarized: N; CompType: Capacitor; Value: 10uF; U/M: EA; Cap_F: 0.00001; Tolerance_%: 20; Value1: Unknown; VDC_V: 6.3; TaMin_C: -55; TaMax_C: 125; Cap_Case: 0805
C23-C25 = C1005X7R1H222K: CAP, CERM, 2200 pF, 50 V, +/- 10%, X7R, 0402; Manufacturer: TDK; Polarized: N; CompType: Capacitor; Value: 2200pF; U/M: EA; Cap_F: 0.0000000022; Tolerance_%: 10; ESR_ohm: 0.1433; Value1: 0.1433 ohm; VDC_V: 50; TaMin_C: -55; TaMax_C: 125
C26 C27 = GRM1885C2A180JA01D: CAP, CERM, 18pF, 100V, +/-5%, C0G/NP0, 0603; Manufacturer: MuRata; Polarized: N; CompType: Capacitor; U/M: EA; Cap_F: 0.000000000018; Tolerance_%: 5; Value1: Unknown; VDC_V: 100; TaMin_C: -55; TaMax_C: 125
D3 = 1SS315TPH3F: Diode, Schottky, 5V, 0.03A, SOD-323; Manufacturer: Toshiba; U/M: EA; Vf_V: 0.38; Value2: 0.38V; Io_A: 0.03; Vr_V: 5; TJmax_C: 125
D4 = SML-P12PTT86: LED, Green, SMD; Manufacturer: Rohm; Type: AlInGaP; Vf_V: 2.2; Value2: 2.2V; Io_A: 0.02; Value1: W; U/M: EA
J4 J5 = TFM-110-02-L-D-A: Straight Low Profile Header, 10x2 Position,1.27 mm Pitch, SMT; Manufacturer: Samtec; SymbolCreator: a0412235; U/M: EA
J6 = LPPB061NFSC-RC: Receptacle, 1.27mm, 6x1, Gold, SMT; Manufacturer: Sullins Connector Solutions; SymbolCreator: a0411947; U/M: EA
L5 = BLM18SG331TN1D: 1.5A Ferrite Bead, 330 ohm @ 100MHz, SMD; Manufacturer: MuRata; Imax_A: 1.5; DCR_ohm: 0.07; Value1: 0.07 ohm; ZTyp@100MHz_Ohm: 330; U/M: EA
Q1 = BSS138: MOSFET, N-CH, 50V, 0.22A, SOT-23; Manufacturer: Fairchild Semiconductor; Alternate Manufacturer: None; U/M: EA; ChType: N; VdsMax_V: 50; Value1: 6 ohm; Rdson45_Ohm: 6; Value2: 1.7 nC; QgTyp_nC: 1.7; Vgs_V: 20; IdsMax_A: 0.22
R2-R15 = CRCW04020000Z0ED: RES, 0 ohm, 5%, 0.063W, 0402; Manufacturer: Vishay-Dale; CompType: Resistor; Value_Code: 0000; Tolerance_%: 5; Power_W: 0.063; VDC_V: 50; TempCo: 200 ppm/C; EIA_Code: E24; U/M: EA
R16 R17 = CRCW04024K99FKED: RES, 4.99k ohm, 1%, 0.063W, 0402; Manufacturer: Vishay-Dale; CompType: Resistor; Res_ohm: 4990; Value_Code: 4k99; Tolerance_%: 1; Power_W: 0.063; VDC_V: 50; TempCo: 100 ppm/C; EIA_Code: E96; U/M: EA
R18-R20 = CRCW040247K5FKED: RES, 47.5 k, 1%, 0.063 W, 0402; Manufacturer: Vishay-Dale; CompType: Resistor; Res_ohm: 47500; Value: 47.5k; Value_Code: 47k5; Tolerance_%: 1; Power_W: 0.063; Value2: 0.063W; VDC_V: 50; TempCo: 100 ppm/C; EIA_Code: E96; U/M: EA
R21 = CRCW0402221RFKED: RES, 221 ohm, 1%, 0.063W, 0402; Manufacturer: Vishay-Dale; CompType: Resistor; Value_Code: 221R; Tolerance_%: 1; Power_W: 0.063; VDC_V: 50; TempCo: 100 ppm/C; EIA_Code: E96; U/M: EA
S1-S3 = 4-1437565-1: Switch, Tactile, SPST-NO, 0.05A, 12V, SMT; Manufacturer: TE Connectivity; SymbolCreator: a0412235; VDC_V: 12; SwitchFunction: Off-Mom; PositionCount: 1; CurrentRating_mA: 50
U5 U6 = TPD1E10B06DPYR: ESD in 0402 Package with 10 pF Capacitance and 6 V Breakdown, 1 Channel, -40 to +125 degC, 2-pin X2SON (DPY), Green (RoHS & no Sb/Br); Manufacturer: Texas Instruments; Alternate Manufacturer: None; Alternate PartNumber: Equivalent; Breakdown Voltage(Min)(V): 6; Eco-Plan: TBD; IEC 61000-4-2 Air-Gap(+/- kV): 30; IO Capacitance(Typ)(pF): 10; SubFamily: ESD Solution
U7 = MSP430FR5969IRGZ: Mixed Signal Microcontroller, RGZ0048B; Alternate Manufacturer: None; Manufacturer: Texas Instruments; SymbolCreator: a0411947; CompType: IC; U/M: EA
Y1 = NX3225GD-8MHZ-STD-CRA-3: Crystal, 8MHz, 5pF, SMD; Manufacturer: NDK; SymbolCreator: a0412235; U/M: EA; TaMin_C: -40; TaMax_C: 150; Frequency Stability: ±150ppm

## Sheet ISE4024_Sheet3.SchDoc: Sensors
size 431 x 279 mm; Date: Not shown in title block; ApprovedBy: Not shown in title block; CheckedBy: Not shown in title block; Author: Not shown in title block; CompanyName: Not shown in title block; DrawnBy: Jarrod Krebs; Engineer: Not shown in title block; Organization: Not shown in title block; Address1: Not shown in title block; Address2: Not shown in title block; Address3: Not shown in title block; Address4: Not shown in title block; DocumentNumber: 5; Revision: Use project parameter SCH_Rev; SheetNumber: 5; SheetTotal: 5; PageSetup: Record=PageOptions¦CenterHorizontal=True¦CenterVertical=True¦PrintScale=1.00¦XCorrection=1.00¦YCorrection=1.00¦PrintKind=0¦BorderSize=5000000¦LeftOffset=0¦BottomOffset=0¦Orientation=2¦PaperLength=1000¦PaperWidth=1000¦Scale=100¦PaperSource=15¦PrintQuality=600¦MediaType=1¦DitherType=10¦PaperKind=Letter¦PrintScaleMode=1
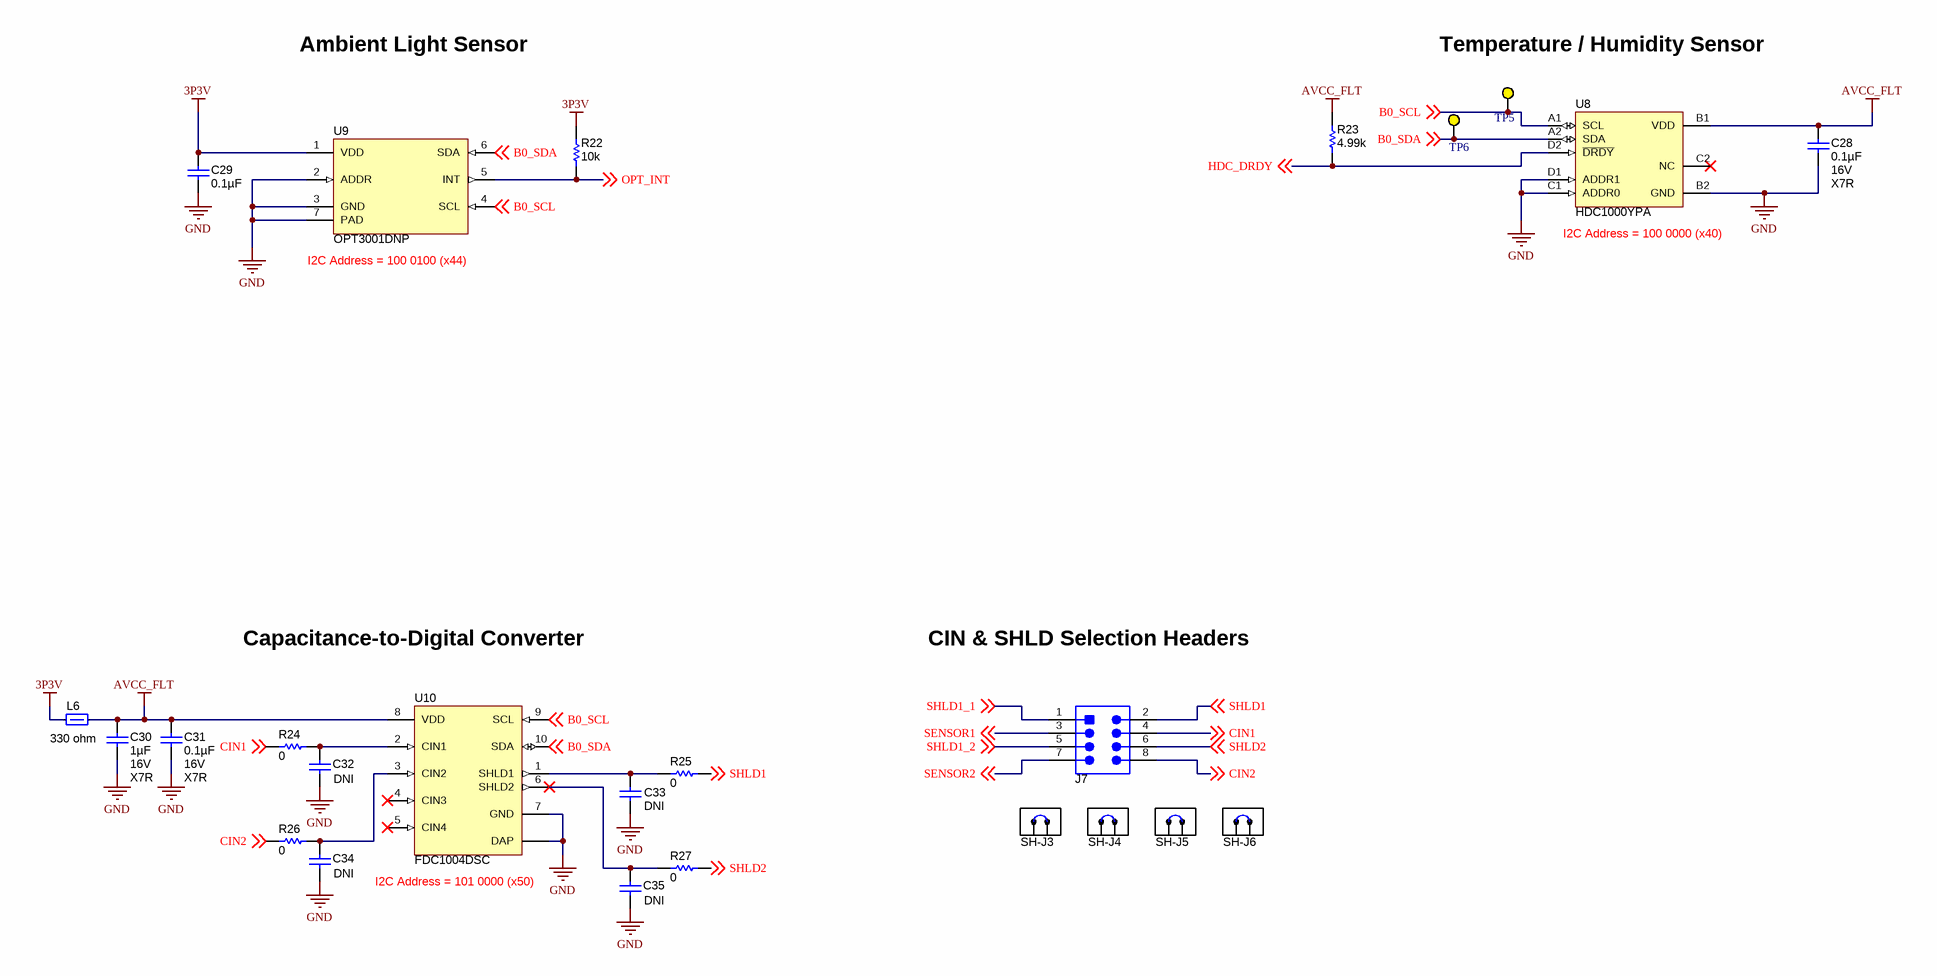
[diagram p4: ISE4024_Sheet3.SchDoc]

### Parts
C28  ValueDisplayed: 0.1µF  Value2: 16V  TempCo: X7R  [0402]  (hidden comment: GRM155R71C104KA88D)
C29  ValueDisplayed: 0.1µF  [0603]  (hidden comment: 06033C104JAT2A)
C30  ValueDisplayed: 1µF  Value2: 16V  TempCo: X7R  [0603]  (hidden comment: C1608X7R1C105K)
C31  ValueDisplayed: 0.1µF  Value2: 16V  TempCo: X7R  [0402]  (hidden comment: GRM155R71C104KA88D)
C32  Used in BOM report  [0402]  (value not drawn)
C33  Used in BOM report  [0402]  (value not drawn)
C34  Used in BOM report  [0402]  (value not drawn)
C35  Used in BOM report  [0402]  (value not drawn)
J7  0015910080  [Molex_0015910080]  (value not drawn)
L6  value 330 ohm  [0603]  (hidden comment: BLM18SG331TN1D)
R22  ValueDisplayed: 10k  [0402]  (hidden comment: CRCW040210K0JNED)
R23  ValueDisplayed: 4.99k  [0402]  (hidden comment: CRCW04024K99FKED)
R24  ValueDisplayed: 0  [0402]  (hidden comment: CRCW04020000Z0ED)
R25  ValueDisplayed: 0  [0402]  (hidden comment: CRCW04020000Z0ED)
R26  ValueDisplayed: 0  [0402]  (hidden comment: CRCW04020000Z0ED)
R27  ValueDisplayed: 0  [0402]  (hidden comment: CRCW04020000Z0ED)
SH-J3  2SN-BK-G  [2SN-BK-G]  (value not drawn)
SH-J4  2SN-BK-G  [2SN-BK-G]  (value not drawn)
SH-J5  2SN-BK-G  [2SN-BK-G]  (value not drawn)
SH-J6  2SN-BK-G  [2SN-BK-G]  (value not drawn)
TP5  5009  [Keystone5009]  (value not drawn)
TP6  5009  [Keystone5009]  (value not drawn)
U8  HDC1000YPA  [YPA0008AGAE]
U9  OPT3001DNP  [DNP0006A]
U10  FDC1004DSC  [DSC0010B]

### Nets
3P3V: C29.1 L6.1 R22.2 U9.1(VDD)
AVCC_FLT: C28.2 C30.1 C31.2 L6.2 R23.2 U8.B1(VDD) U10.8(VDD)
GND: C28.1 C29.2 C30.2 C31.1 C32.1 C33.2 C34.1 C35.1 U8.B2(GND) U8.C1(ADDR0) U8.D1(ADDR1) U9.2(ADDR) U9.3(GND) U9.7(PAD) U10.7(GND) U10.11(DAP)
B0_SCL: TP5.1 U8.A1(SCL) U9.4(SCL) U10.9(SCL) ; off-sheet B0_SCL
B0_SDA: TP6.1 U8.A2(SDA) U9.6(SDA) U10.10(SDA) ; off-sheet B0_SDA
CIN1: J7.4 R24.1 ; off-sheet CIN1
CIN2: J7.8 R26.1 ; off-sheet CIN2
HDC_DRDY: R23.1 U8.D2(~{DRDY}) ; off-sheet HDC_DRDY
OPT_INT: R22.1 U9.5(INT) ; off-sheet OPT_INT
SENSOR1: J7.3 ; off-sheet SENSOR1
SENSOR2: J7.7 ; off-sheet SENSOR2
SHLD1: J7.2 R25.2 ; off-sheet SHLD1
SHLD1_1: J7.1 ; off-sheet SHLD1_1
SHLD1_2: J7.5 ; off-sheet SHLD1_2
SHLD2: J7.6 R27.2 ; off-sheet SHLD2
NetC32_2: C32.2 R24.2 U10.2(CIN1)
NetC33_1: C33.1 R25.1 U10.1(SHLD1)
NetC34_2: C34.2 R26.2 U10.3(CIN2)
NetC35_2: C35.2 R27.1 U10.6(SHLD2)

Not connected (* = marked no-connect by the designer): U8 C2(NC)*; U10 4(CIN3)* 5(CIN4)*

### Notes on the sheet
- Ambient Light Sensor
- (near TP5) Temperature / Humidity Sensor
- (near U9) I2C Address = 100 0100 (x44)
- (near U8) I2C Address = 100 0000 (x40)
- Capacitance-to-Digital Converter
- CIN & SHLD Selection Headers
- I2C Address = 101 0000 (x50)

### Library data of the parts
C28 C31 = GRM155R71C104KA88D: as C17 on sheet ISE4024_Sheet2
C29 = 06033C104JAT2A: CAP, CERM, 0.1 µF, 25 V, +/- 5%, X7R, 0603; Manufacturer: AVX; Polarized: N; CompType: Capacitor; Value: 0.1uF; U/M: EA; Cap_F: 0.0000001; Tolerance_%: 5; ESR_ohm: 0.05; Value1: 0.05 ohm; VDC_V: 25; Value2: 25V; TaMin_C: -55; TaMax_C: 125
C30 = C1608X7R1C105K: as C5 on sheet ISE4024_Sheet1
C32-C35 = Capacitor: CAP, CERM, xxxF, xxV, [TempCo], xx%, [PackageReference]; Polarized: N; U/M: EA
J7 = 0015910080: Header, 100mil, 4x2, Gold, SMT; Manufacturer: Molex; SymbolCreator: a0411947; U/M: EA
L6 = BLM18SG331TN1D: as L5 on sheet ISE4024_Sheet2
R22 = CRCW040210K0JNED: RES, 10 k, 5%, 0.063 W, 0402; Manufacturer: Vishay-Dale; CompType: Resistor; Value: 10k; Res_ohm: 10000; Value_Code: 10k0; Tolerance_%: 5; Power_W: 0.063; Value2: 0.063W; VDC_V: 50; TempCo: 200 ppm/C; EIA_Code: E24; U/M: EA
R23 = CRCW04024K99FKED: RES, 4.99 k, 1%, 0.063 W, 0402; Manufacturer: Vishay-Dale; CompType: Resistor; Value: 4.99k; Res_ohm: 4990; Value_Code: 4k99; Tolerance_%: 1; Power_W: 0.063; Value2: 0.063W; VDC_V: 50; TempCo: 100 ppm/C; EIA_Code: E96; U/M: EA
R24-R27 = CRCW04020000Z0ED: RES, 0, 5%, 0.063 W, 0402; Manufacturer: Vishay-Dale; CompType: Resistor; Value: 0; Value_Code: 0000; Tolerance_%: 5; Power_W: 0.063; Value2: 0.063W; VDC_V: 50; TempCo: 200 ppm/C; EIA_Code: E24; U/M: EA
SH-J3-SH-J6 = 2SN-BK-G: as SH-J1 on sheet ISE4024_Sheet1
TP5 TP6 = 5009: Test Point, Compact, Yellow, TH; Manufacturer: Keystone; CompType: Test Point Loop; U/M: EA
U8 = HDC1000YPA: HDC1000 Low power integrated humidity and temperature Sensor, YPA0008AGAE; Manufacturer: Texas Instruments; SymbolCreator: a0411947; CompType: IC; U/M: EA
U9 = OPT3001DNP: Ambient Light Sensor, DNP0006A; Alternate Manufacturer: None; Manufacturer: Texas Instruments; SymbolCreator: a0411947; CompType: IC; U/M: EA
U10 = FDC1004DSC: 4-Channel Capacitance-to-Digital Converter for Capacitive Sensing Solutions, DSC0010B; Alternate Manufacturer: None; Manufacturer: Texas Instruments; SymbolCreator: x0208325; CompType: IC; U/M: EA

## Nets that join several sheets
3P3V: ISE4024_Sheet1 (8 pins), ISE4024_Sheet2 (13 pins), ISE4024_Sheet3 (C29.1 L6.1 R22.2 U9.1)
GND: ISE4024_Sheet1 (19 pins), ISE4024_Sheet2 (30 pins), ISE4024_Sheet3 (16 pins)
A0_SCLK: ISE4024_Sheet1 (U3.37), ISE4024_Sheet2 (R13.2 U7.11)
A0_SIMO: ISE4024_Sheet1 (U3.36), ISE4024_Sheet2 (R14.2 U7.24)
B0_SCL: ISE4024_Sheet1 (U4.A2), ISE4024_Sheet2 (R16.1 U7.32), ISE4024_Sheet3 (TP5.1 U8.A1 U9.4 U10.9)
B0_SDA: ISE4024_Sheet1 (U4.A1), ISE4024_Sheet2 (R17.1 U7.31), ISE4024_Sheet3 (TP6.1 U8.A2 U9.6 U10.10)
BL_EN: ISE4024_Sheet1 (U4.B1), ISE4024_Sheet2 (U7.7)
BL_PWM: ISE4024_Sheet1 (U4.C1), ISE4024_Sheet2 (U7.26)
HDC_DRDY: ISE4024_Sheet2 (U7.3), ISE4024_Sheet3 (R23.1 U8.D2)
LCD_A0: ISE4024_Sheet1 (U3.38), ISE4024_Sheet2 (U7.6)
nCSB_LCD: ISE4024_Sheet1 (U3.40), ISE4024_Sheet2 (U7.10)
nRST_LCD: ISE4024_Sheet1 (U3.39), ISE4024_Sheet2 (U7.5)
OPT_INT: ISE4024_Sheet2 (U7.9), ISE4024_Sheet3 (R22.1 U9.5)

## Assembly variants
001: not fitted C26 C27 C32 C33 C34 C35 FID1 FID2 FID3 FID4 FID5 FID6 R2 R4 R6 Y1 ZZ1 ZZ2 ZZ3 ZZ4 ZZ5 ZZ6 ZZ7 ZZ8 ZZ9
